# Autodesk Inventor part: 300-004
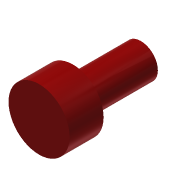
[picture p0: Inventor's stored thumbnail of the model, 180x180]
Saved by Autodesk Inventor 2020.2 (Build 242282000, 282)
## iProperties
Created: 2014-01
Part Number: 300-004
Material: Ogólny
Document SubType Name: Modeling
Designer: F.Stasiak
Density: 1 g/cm^3
Appearance: Czerwona
Manager: www.cadconsulting.pl
Company: Fabian Stasiak CAD Consulting
Author: F.Stasiak
Subject: Zbiór ćwiczeń. Autodesk Inventor 2020. Kurs podstawowy
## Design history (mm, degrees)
sketch "Szkic1"
  geometry: C1 r 5 at (0, 0); 1 further point
  constraints: 1 centre point, 1 coincident
  dimensions: "d0" = 10 diameter of C1
extrude "Wyciągnięcie proste1" new body sketch "Szkic1" distance "d1" = 20; taper "d2" = 0 deg
sketch "Szkic2"
  geometry: C1 r 5 at (0, 0) reference; C2 r 9 at (0, 0)
  constraints: 1 centre point, 1 coincident
  dimensions: "d3" = 18 diameter of C2
extrude "Wyciągnięcie proste2" join sketch "Szkic2" distance "d4" = 10; taper "d5" = 0 deg
node "Bryła1"
